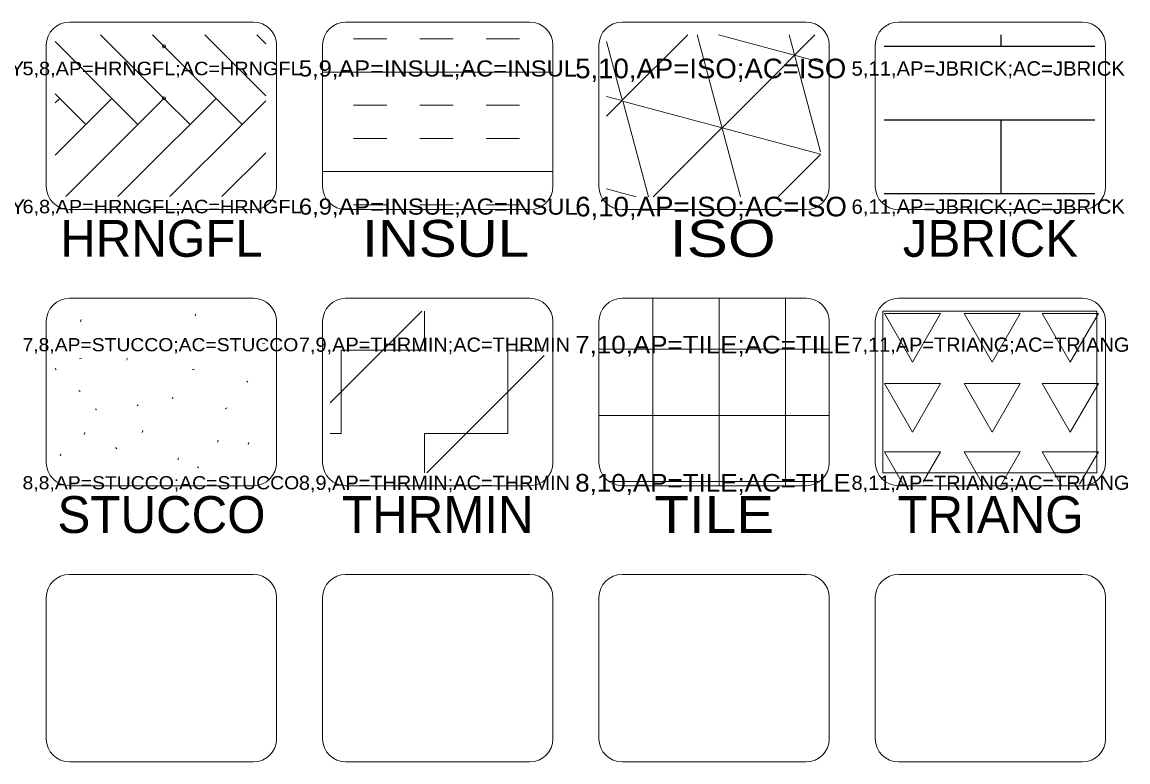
# Model space of a CAD drawing. Extents: x 95935 to 95946.4, y 95971.2 to 95974.7.
# Drawn here: x 95939.233 to 95941.634, y 95971.925 to 95973.532 of the extents above; entities that cross this region are included whole.
import ezdxf
from ezdxf.enums import TextEntityAlignment as Align

# ---------------------------------------------------------------- set-up
doc = ezdxf.new("R2010")
doc.units = 0
doc.header["$LTSCALE"] = 0.013
doc.header["$PDMODE"] = 32
doc.header["$PDSIZE"] = 0.0065
for name, color, linetype, lineweight in [('1', 7, 'Continuous', 13), ('6', 7, 'Continuous', 13), ('63', 7, 'Continuous', 13)]:
    doc.layers.add(name, color=color, linetype=linetype, lineweight=lineweight)
doc.layers.add('20', color=7, linetype='Continuous')

msp = doc.modelspace()

# ---------------------------------------------------------------- linework, layer by layer
at = {"layer": '1'}
for p, q in [((95939.3357, 95973.5318), (95939.7357, 95973.5318)), ((95939.9357, 95973.5318), (95940.3357, 95973.5318)), ((95940.5357, 95973.5318), (95940.9357, 95973.5318)), ((95941.1357, 95973.5318), (95941.5357, 95973.5318)), ((95939.2857, 95973.1747), (95939.2857, 95973.4818)), ((95939.7857, 95973.4818), (95939.7857, 95973.1747)), ((95939.8857, 95973.1747), (95939.8857, 95973.4818)), ((95940.3857, 95973.4818), (95940.3857, 95973.1747)), ((95940.4857, 95973.1747), (95940.4857, 95973.4818)), ((95940.9857, 95973.4818), (95940.9857, 95973.1747)), ((95941.0857, 95973.1747), (95941.0857, 95973.4818)), ((95941.5857, 95973.4818), (95941.5857, 95973.1747)), ((95939.7357, 95973.1247), (95939.3357, 95973.1247)), ((95940.3357, 95973.1247), (95939.9357, 95973.1247)), ((95940.9357, 95973.1247), (95940.5357, 95973.1247)), ((95941.5357, 95973.1247), (95941.1357, 95973.1247)), ((95939.3357, 95972.9318), (95939.7357, 95972.9318)), ((95939.9357, 95972.9318), (95940.3357, 95972.9318)), ((95940.5357, 95972.9318), (95940.9357, 95972.9318)), ((95941.1357, 95972.9318), (95941.5357, 95972.9318)), ((95939.2857, 95972.5747), (95939.2857, 95972.8818)), ((95939.7857, 95972.8818), (95939.7857, 95972.5747)), ((95939.8857, 95972.5747), (95939.8857, 95972.8818)), ((95940.3857, 95972.8818), (95940.3857, 95972.5747)), ((95940.4857, 95972.5747), (95940.4857, 95972.8818)), ((95940.9857, 95972.8818), (95940.9857, 95972.5747)), ((95941.0857, 95972.5747), (95941.0857, 95972.8818)), ((95941.5857, 95972.8818), (95941.5857, 95972.5747)), ((95939.7357, 95972.5247), (95939.3357, 95972.5247)), ((95940.3357, 95972.5247), (95939.9357, 95972.5247)), ((95940.9357, 95972.5247), (95940.5357, 95972.5247)), ((95941.5357, 95972.5247), (95941.1357, 95972.5247)), ((95939.3357, 95972.3318), (95939.7357, 95972.3318)), ((95939.9357, 95972.3318), (95940.3357, 95972.3318)), ((95940.5357, 95972.3318), (95940.9357, 95972.3318)), ((95941.1357, 95972.3318), (95941.5357, 95972.3318)), ((95939.2857, 95971.9747), (95939.2857, 95972.2818)), ((95939.7857, 95972.2818), (95939.7857, 95971.9747)), ((95939.8857, 95971.9747), (95939.8857, 95972.2818)), ((95940.3857, 95972.2818), (95940.3857, 95971.9747)), ((95940.4857, 95971.9747), (95940.4857, 95972.2818)), ((95940.9857, 95972.2818), (95940.9857, 95971.9747)), ((95941.0857, 95971.9747), (95941.0857, 95972.2818)), ((95941.5857, 95972.2818), (95941.5857, 95971.9747)), ((95939.7357, 95971.9247), (95939.3357, 95971.9247)), ((95940.3357, 95971.9247), (95939.9357, 95971.9247)), ((95940.9357, 95971.9247), (95940.5357, 95971.9247)), ((95941.5357, 95971.9247), (95941.1357, 95971.9247))]:
    msp.add_line(p, q, dxfattribs=at)
for centre, start, end in [((95939.3357, 95973.4818), 90, 180), ((95939.7357, 95973.4818), 0, 90), ((95939.9357, 95973.4818), 90, 180), ((95940.3357, 95973.4818), 0, 90), ((95940.5357, 95973.4818), 90, 180), ((95940.9357, 95973.4818), 0, 90), ((95941.1357, 95973.4818), 90, 180), ((95941.5357, 95973.4818), 0, 90), ((95939.3357, 95973.1747), 180, 270), ((95939.7357, 95973.1747), 270, 0), ((95939.9357, 95973.1747), 180, 270), ((95940.3357, 95973.1747), 270, 0), ((95940.5357, 95973.1747), 180, 270), ((95940.9357, 95973.1747), 270, 0), ((95941.1357, 95973.1747), 180, 270), ((95941.5357, 95973.1747), 270, 0), ((95939.3357, 95972.8818), 90, 180), ((95939.7357, 95972.8818), 0, 90), ((95939.9357, 95972.8818), 90, 180), ((95940.3357, 95972.8818), 0, 90), ((95940.5357, 95972.8818), 90, 180), ((95940.9357, 95972.8818), 0, 90), ((95941.1357, 95972.8818), 90, 180), ((95941.5357, 95972.8818), 0, 90), ((95939.3357, 95972.5747), 180, 270), ((95939.7357, 95972.5747), 270, 0), ((95939.9357, 95972.5747), 180, 270), ((95940.3357, 95972.5747), 270, 0), ((95940.5357, 95972.5747), 180, 270), ((95940.9357, 95972.5747), 270, 0), ((95941.1357, 95972.5747), 180, 270), ((95941.5357, 95972.5747), 270, 0), ((95939.3357, 95972.2818), 90, 180), ((95939.7357, 95972.2818), 0, 90), ((95939.9357, 95972.2818), 90, 180), ((95940.3357, 95972.2818), 0, 90), ((95940.5357, 95972.2818), 90, 180), ((95940.9357, 95972.2818), 0, 90), ((95941.1357, 95972.2818), 90, 180), ((95941.5357, 95972.2818), 0, 90), ((95939.3357, 95971.9747), 180, 270), ((95939.7357, 95971.9747), 270, 0), ((95939.9357, 95971.9747), 180, 270), ((95940.3357, 95971.9747), 270, 0), ((95940.5357, 95971.9747), 180, 270), ((95940.9357, 95971.9747), 270, 0), ((95941.1357, 95971.9747), 180, 270), ((95941.5357, 95971.9747), 270, 0)]:
    msp.add_arc(centre, 0.05, start, end, dxfattribs=at)
at = {"layer": '6', "lineweight": 25}
for p, q in [((95939.4034, 95973.504), (95939.4281, 95973.4793)), ((95939.5165, 95973.504), (95939.5412, 95973.4793)), ((95939.6297, 95973.504), (95939.6544, 95973.4793)), ((95939.7428, 95973.504), (95939.7622, 95973.4846)), ((95941.359, 95973.4796), (95941.359, 95973.504)), ((95939.3048, 95973.4894), (95939.3149, 95973.4793)), ((95939.4281, 95973.3662), (95939.3149, 95973.4793)), ((95939.5412, 95973.3662), (95939.4281, 95973.4793)), ((95939.6543, 95973.3662), (95939.5412, 95973.4793)), ((95939.7622, 95973.3715), (95939.6544, 95973.4793)), ((95941.1048, 95973.4796), (95941.5622, 95973.4796)), ((95939.3149, 95973.3662), (95939.3048, 95973.3763)), ((95939.3149, 95973.3662), (95939.3048, 95973.3561)), ((95939.3149, 95973.3662), (95939.3715, 95973.3096)), ((95939.4281, 95973.3662), (95939.3715, 95973.3096)), ((95939.4281, 95973.3662), (95939.4847, 95973.3096)), ((95939.5412, 95973.3662), (95939.4846, 95973.3096)), ((95939.5412, 95973.3662), (95939.5978, 95973.3096)), ((95939.6543, 95973.3662), (95939.5978, 95973.3096)), ((95939.6543, 95973.3662), (95939.7109, 95973.3096)), ((95939.7622, 95973.3609), (95939.7109, 95973.3096)), ((95939.3048, 95973.2429), (95939.3715, 95973.3096)), ((95939.3278, 95973.1527), (95939.4847, 95973.3096)), ((95939.5412, 95973.2531), (95939.5978, 95973.3096)), ((95939.554, 95973.1527), (95939.7109, 95973.3096)), ((95941.1048, 95973.3196), (95941.5622, 95973.3196)), ((95941.359, 95973.1596), (95941.359, 95973.3196)), ((95939.4408, 95973.1527), (95939.5412, 95973.2531)), ((95939.6671, 95973.1527), (95939.7622, 95973.2477)), ((95941.1048, 95973.1596), (95941.5622, 95973.1596))]:
    msp.add_line(p, q, dxfattribs=at)
at = {"layer": '6'}
for p, q in [((95939.953, 95973.4952), (95940.025, 95973.4952)), ((95939.953, 95973.4952), (95940.025, 95973.4952)), ((95940.097, 95973.4952), (95940.169, 95973.4952)), ((95940.097, 95973.4952), (95940.169, 95973.4952)), ((95940.241, 95973.4952), (95940.313, 95973.4952)), ((95940.241, 95973.4952), (95940.313, 95973.4952)), ((95940.5364, 95973.3619), (95940.6783, 95973.5038)), ((95940.7931, 95973.1523), (95940.699, 95973.5038)), ((95940.7455, 95973.5038), (95940.9667, 95973.4445)), ((95940.8321, 95973.3812), (95940.9547, 95973.5038)), ((95940.9667, 95973.2498), (95940.8986, 95973.5038)), ((95940.5369, 95973.36), (95940.5021, 95973.4899)), ((95939.8857, 95973.4232), (95940.3857, 95973.4232)), ((95940.6746, 95973.2237), (95940.8314, 95973.3805)), ((95939.953, 95973.3512), (95940.025, 95973.3512)), ((95939.953, 95973.3512), (95940.025, 95973.3512)), ((95940.097, 95973.3512), (95940.169, 95973.3512)), ((95940.097, 95973.3512), (95940.169, 95973.3512)), ((95940.241, 95973.3512), (95940.313, 95973.3512)), ((95940.241, 95973.3512), (95940.313, 95973.3512)), ((95940.385, 95973.3512), (95940.3857, 95973.3512)), ((95940.385, 95973.3512), (95940.3857, 95973.3512)), ((95940.5021, 95973.3702), (95940.535, 95973.3614)), ((95940.5021, 95973.3276), (95940.5357, 95973.3612)), ((95940.5369, 95973.36), (95940.9665, 95973.2449)), ((95940.5935, 95973.1523), (95940.5383, 95973.3581)), ((95939.953, 95973.2792), (95940.025, 95973.2792)), ((95939.953, 95973.2792), (95940.025, 95973.2792)), ((95940.097, 95973.2792), (95940.169, 95973.2792)), ((95940.097, 95973.2792), (95940.169, 95973.2792)), ((95940.241, 95973.2792), (95940.313, 95973.2792)), ((95940.241, 95973.2792), (95940.313, 95973.2792)), ((95940.385, 95973.2792), (95940.3857, 95973.2792)), ((95940.385, 95973.2792), (95940.3857, 95973.2792)), ((95940.8747, 95973.1523), (95940.9667, 95973.2442)), ((95939.8857, 95973.2072), (95940.3857, 95973.2072)), ((95940.6032, 95973.1523), (95940.6739, 95973.223)), ((95940.5021, 95973.1696), (95940.5668, 95973.1523)), ((95939.953, 95973.1352), (95940.025, 95973.1352)), ((95939.953, 95973.1352), (95940.025, 95973.1352)), ((95940.097, 95973.1352), (95940.169, 95973.1352)), ((95940.097, 95973.1352), (95940.169, 95973.1352)), ((95940.241, 95973.1352), (95940.313, 95973.1352)), ((95940.241, 95973.1352), (95940.313, 95973.1352)), ((95940.6024, 95972.9318), (95940.6024, 95972.5247)), ((95940.7464, 95972.9318), (95940.7464, 95972.5247)), ((95940.8904, 95972.9318), (95940.8904, 95972.5247)), ((95939.6089, 95972.8934), (95939.6104, 95972.8979)), ((95939.9021, 95972.7048), (95940.101, 95972.9038)), ((95940.107, 95972.8192), (95940.107, 95972.9038)), ((95939.3597, 95972.8809), (95939.3612, 95972.8854)), ((95939.5905, 95972.8388), (95939.5858, 95972.8378)), ((95939.7601, 95972.8346), (95939.7554, 95972.8336)), ((95939.3622, 95972.8012), (95939.3576, 95972.8002)), ((95939.4602, 95972.7973), (95939.4617, 95972.8018)), ((95940.1117, 95972.5523), (95940.3667, 95972.8073)), ((95940.2881, 95972.7287), (95940.2881, 95972.8192)), ((95940.2881, 95972.8192), (95940.3667, 95972.8192)), ((95940.4857, 95972.8215), (95940.9857, 95972.8215)), ((95939.3072, 95972.7767), (95939.3049, 95972.779)), ((95939.6072, 95972.7782), (95939.6026, 95972.7772)), ((95939.7234, 95972.7498), (95939.7212, 95972.752)), ((95939.3589, 95972.7296), (95939.3567, 95972.7318)), ((95939.926, 95972.6381), (95939.926, 95972.7287)), ((95939.5614, 95972.7139), (95939.5592, 95972.7161)), ((95939.3949, 95972.6892), (95939.3927, 95972.6914)), ((95939.4849, 95972.6982), (95939.4827, 95972.7004)), ((95939.6784, 95972.6937), (95939.6739, 95972.6914)), ((95940.4857, 95972.6775), (95940.9857, 95972.6775)), ((95939.3682, 95972.6359), (95939.3697, 95972.6404)), ((95939.4938, 95972.6401), (95939.4953, 95972.6446)), ((95939.9021, 95972.6381), (95939.926, 95972.6381)), ((95940.107, 95972.5523), (95940.107, 95972.6381)), ((95939.4385, 95972.6051), (95939.4362, 95972.6074)), ((95939.6571, 95972.6192), (95939.6586, 95972.6237)), ((95939.724, 95972.6144), (95939.7255, 95972.6188)), ((95939.3158, 95972.5893), (95939.3173, 95972.5938)), ((95939.5712, 95972.5809), (95939.5727, 95972.5854)), ((95939.6165, 95972.5633), (95939.6142, 95972.5656)), ((95940.5091, 95972.5335), (95940.9623, 95972.5335))]:
    msp.add_line(p, q, dxfattribs=at)
for points in [[(95941.1021, 95972.9038), (95941.5667, 95972.9038), (95941.5667, 95972.5523), (95941.1021, 95972.5523)], [(95941.1664, 95972.7927), (95941.2275, 95972.8986), (95941.1053, 95972.8986)], [(95941.3394, 95972.7927), (95941.4005, 95972.8986), (95941.2783, 95972.8986)], [(95941.5089, 95972.7927), (95941.57, 95972.8986), (95941.4478, 95972.8986)], [(95941.1664, 95972.6409), (95941.2275, 95972.7468), (95941.1053, 95972.7468)], [(95941.3394, 95972.6409), (95941.4005, 95972.7468), (95941.2783, 95972.7468)], [(95941.5089, 95972.6409), (95941.57, 95972.7468), (95941.4478, 95972.7468)]]:
    msp.add_lwpolyline(points, close=True, dxfattribs=at)
for points in [[(95939.926, 95972.7287), (95939.926, 95972.8192), (95940.107, 95972.8192)], [(95940.107, 95972.6381), (95940.2881, 95972.6381), (95940.2881, 95972.7287)], [(95941.1898, 95972.5331), (95941.2275, 95972.5985), (95941.1053, 95972.5985), (95941.1478, 95972.525)], [(95941.3567, 95972.5226), (95941.4005, 95972.5985), (95941.2783, 95972.5985), (95941.3216, 95972.5235)], [(95941.5293, 95972.5279), (95941.57, 95972.5985), (95941.4478, 95972.5985), (95941.4903, 95972.525)]]:
    msp.add_lwpolyline(points, dxfattribs=at)
for p in [(95939.5412, 95973.4793), (95939.5412, 95973.3662)]:
    msp.add_point(p, dxfattribs=at)

# ---------------------------------------------------------------- texts
at = {"layer": '20'}
for s, p in [('HRNGFL', (95939.5358, 95973.022)), ('JBRICK', (95941.3357, 95973.022)), ('STUCCO', (95939.5358, 95972.422)), ('THRMIN', (95940.1358, 95972.422)), ('TRIANG', (95941.3358, 95972.422))]:
    msp.add_text(s, height=0.08, dxfattribs=at).set_placement(p, align=Align.CENTER)
for s, width, p in [(' INSUL', 1.15, (95940.1357, 95973.022)), ('  ISO ', 1.25, (95940.7358, 95973.022)), (' TILE ', 1.15, (95940.7358, 95972.422))]:
    msp.add_text(s, height=0.08, dxfattribs=dict(at, width=width)).set_placement(p, align=Align.CENTER)
at = {"layer": '63'}
for s, height, width, p in [('5,7,AP=HONEY;AC=HONEY', 0.0317, 1.1, (95938.6341, 95973.4152)), ('5,8,AP=HRNGFL;AC=HRNGFL', 0.0293, 1.1, (95939.2341, 95973.4164)), ('5,9,AP=INSUL;AC=INSUL', 0.035, 1.1, (95939.8341, 95973.4136)), ('5,10,AP=ISO;AC=ISO', 0.0426, 1.05, (95940.4341, 95973.4098)), ('5,11,AP=JBRICK;AC=JBRICK', 0.0313, 1.05, (95941.0341, 95973.4154)), ('6,7,AP=HONEY;AC=HONEY', 0.0318, 1.1, (95938.6341, 95973.1152)), ('6,8,AP=HRNGFL;AC=HRNGFL', 0.0293, 1.1, (95939.2341, 95973.1164)), ('6,9,AP=INSUL;AC=INSUL', 0.0351, 1.1, (95939.8341, 95973.1135)), ('6,10,AP=ISO;AC=ISO', 0.0427, 1.05, (95940.4341, 95973.1097)), ('6,11,AP=JBRICK;AC=JBRICK', 0.0313, 1.05, (95941.0341, 95973.1154)), ('7,8,AP=STUCCO;AC=STUCCO', 0.0285, 1.1, (95939.2341, 95972.8168)), ('7,9,AP=THRMIN;AC=THRMIN', 0.0308, 1.05, (95939.8341, 95972.8157)), ('7,10,AP=TILE;AC=TILE', 0.0383, 1.1, (95940.4341, 95972.8119)), ('7,11,AP=TRIANG;AC=TRIANG', 0.0308, 1.05, (95941.0341, 95972.8157)), ('8,8,AP=STUCCO;AC=STUCCO', 0.0286, 1.1, (95939.2341, 95972.5168)), ('8,9,AP=THRMIN;AC=THRMIN', 0.0308, 1.05, (95939.8341, 95972.5157)), ('8,10,AP=TILE;AC=TILE', 0.0383, 1.1, (95940.4341, 95972.5119)), ('8,11,AP=TRIANG;AC=TRIANG', 0.0308, 1.05, (95941.0341, 95972.5157))]:
    msp.add_text(s, height=height, dxfattribs=dict(at, width=width)).set_placement(p)

doc.saveas('drawing.dxf')
